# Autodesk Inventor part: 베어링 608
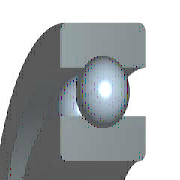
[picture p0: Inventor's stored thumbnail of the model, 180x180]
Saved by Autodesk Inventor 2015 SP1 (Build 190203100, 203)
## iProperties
IsCustomPart: 1
Company: 한국ATC센터
Created: 2014-07
Part Number: 베어링 608
Material: 강, 연강
Description: 깊은 그루브 볼 베어링
Document SubType Name: Modeling
Standard: KS B 2023
Designer: KYOUNG IL JANG
Standards Organization: KS
Language: ko-KR
Size Designation: 608 - 8 x 22 x 7
Categories: <MemberInstance><Categories><Category DisplayName="샤프트 부품" InternalName="7f7aeb1f-a693-4053-b835-cee3144e0d98" Mnemonic="SHFT"><Category DisplayName="베어링" Inter
Density: 1 g/cm^3
Appearance: 강철
Author: KYOUNG IL JANG
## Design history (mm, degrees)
sketch "스케치" dims "d0" = 3.64 (= -0.26 x WD + 0.26 x BD)
  geometry: L1 (1.68, 7.5)-(5.32, 7.5); L2 (3.5, 7.5)-(3.5, 5.68); L3 (3.5, 7.5)-(3.5, 9.32); L4 (2.148, 6.282)-(0, 6.282); L5 (0, 4)-(7, 4); L6 (2.148, 8.718)-(0, 8.718); L7 (0, 11)-(7, 11); L8 (7, 4)-(7, 6.282); L9 (4.852, 6.282)-(7, 6.282); L10 (4.852, 8.718)-(7, 8.718); L11 (7, 11)-(7, 8.718); L12 (-1.4, 0)-(8.4, 0) reference; L13 (0, -0.3)-(0, 5.3) reference
  constraints: 22 end point, 4 point on line, 2 collinear, 2 perpendicular, 2 symmetric about line, 1 midpoint, 1 parallel, 14 other
  dimensions: "d9" = 8 diameter of L5 L12 (= WD); "d11" = 22 diameter of L7 L12 (= BD); "d12" = 7 distance between parallel lines of L8 L13 (= KB); "d13" = 12.564 diameter of L9 L12 (= 0.326 x BD + 0.674 x WD)
revolve "본체" stored, may be unused: angle "d6" = 90 deg
revolve "볼" stored, may be unused: angle "d7" = 90 deg
pattern_circular "IDS_ARRAYBALL[SIMPL:T]" dims angle "d3" = 360 deg
body "Solid1"
fillet "모깎기1" dims "d1" = 0.3 (= KRS)
other parameters: "WD" = 8 [user parameter; used in 5 equation terms], "BD" = 22 [user parameter; used in 5 equation terms], "KB" = 7 [user parameter; used in 1 equation term], "KRS" = 0.3 [user parameter; used in 1 equation term], "d4" = 0, "d5" = 0, "d8" = 0, "d14" = 0, "d15" = 0, "BBA" = 0 [user parameter], "BC0" = 1370000 [user parameter], "BC" = 3250000 [user parameter], "BR" = 11 (= 0.5 x BD) [user parameter], "WR" = 4 (= 0.5 x WD) [user parameter]
